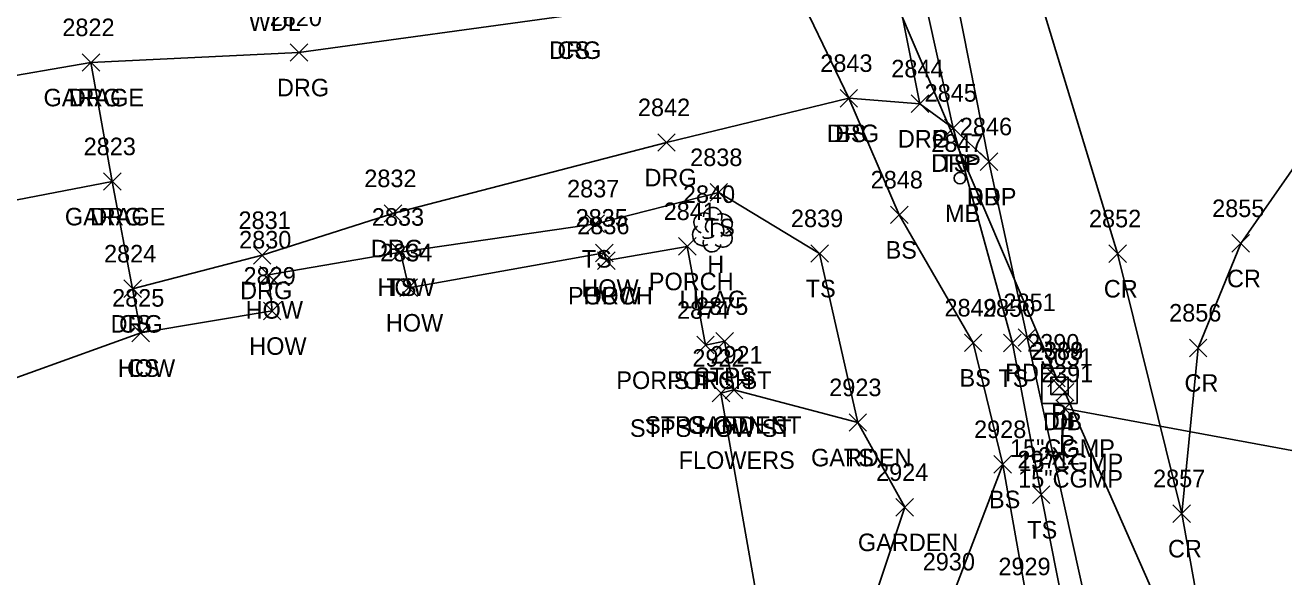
# Model space of a CAD drawing. Extents: x 1504228 to 1506103, y 437717 to 440106.
# Drawn here: x 1505128.7 to 1505272.1, y 438016.6 to 438079.5 of the extents above; entities that cross this region are included whole.
import ezdxf

# ---------------------------------------------------------------- set-up
doc = ezdxf.new("R2010")
doc.units = 0
for name, color, linetype in [('D_A', 7, 'Continuous'), ('D_C', 7, 'Continuous'), ('D_I', 7, 'Continuous'), ('D_TIC', 7, 'Continuous'), ('DCP', 7, 'Continuous'), ('DS', 7, 'Continuous'), ('L_A', 7, 'Continuous'), ('L_C', 7, 'Continuous'), ('L_I', 7, 'Continuous'), ('L_TIC', 7, 'Continuous'), ('LAPB', 7, 'Continuous'), ('LBC', 7, 'Continuous'), ('LBF', 7, 'Continuous'), ('LELB', 7, 'Continuous'), ('LMB', 7, 'Continuous'), ('LTD', 7, 'Continuous'), ('P_A', 7, 'Continuous'), ('P_I', 7, 'Continuous'), ('P_TIC', 7, 'Continuous'), ('PET', 7, 'Continuous'), ('PRC', 7, 'Continuous'), ('R_A', 7, 'Continuous'), ('R_I', 7, 'Continuous'), ('R_TIC', 7, 'Continuous'), ('RDG', 7, 'Continuous'), ('RDP', 7, 'Continuous')]:
    doc.layers.add(name, color=color, linetype=linetype)

msp = doc.modelspace()

# ---------------------------------------------------------------- linework, layer by layer
at = {"layer": 'D_TIC'}
for points in [[(1505245.19, 438038.31), (1505247.19, 438040.31)], [(1505247.19, 438038.31), (1505245.19, 438040.31)], [(1505245.55, 438037.35), (1505247.55, 438039.35)], [(1505247.55, 438037.35), (1505245.55, 438039.35)], [(1505246.15, 438036.69), (1505248.15, 438038.69)], [(1505248.15, 438036.69), (1505246.15, 438038.69)], [(1505246.12, 438034.81), (1505248.12, 438036.81)], [(1505248.12, 438034.81), (1505246.12, 438036.81)]]:
    msp.add_lwpolyline(points, dxfattribs=at)
at = {"layer": 'DCP'}
for points in [[(1505203.94, 438138.28), (1505246.19, 438039.31)], [(1505304.61, 437907.19), (1505247.15, 438037.69)], [(1505247.12, 438035.81), (1505284.73, 438028.89)]]:
    msp.add_lwpolyline(points, dxfattribs=at)
at = {"layer": 'DS'}
for p, q in [((1505244.53, 438040.41), (1505248.53, 438040.41)), ((1505244.53, 438036.41), (1505244.53, 438040.41)), ((1505248.53, 438040.41), (1505248.53, 438036.41)), ((1505245.53, 438037.41), (1505245.53, 438039.41)), ((1505245.53, 438039.41), (1505247.53, 438039.41)), ((1505247.53, 438039.41), (1505247.53, 438037.41)), ((1505247.53, 438037.41), (1505245.53, 438037.41)), ((1505246.54, 438038.41), (1505246.54, 438038.41)), ((1505246.54, 438038.41), (1505246.54, 438038.41)), ((1505248.53, 438036.41), (1505244.53, 438036.41))]:
    msp.add_line(p, q, dxfattribs=at)
at = {"layer": 'L_TIC'}
for points in [[(1505135.2, 438074.26), (1505137.2, 438076.26)], [(1505137.2, 438074.26), (1505135.2, 438076.26)], [(1505221.54, 438070.18), (1505223.54, 438072.18)], [(1505223.54, 438070.18), (1505221.54, 438072.18)], [(1505233.43, 438066.79), (1505235.43, 438068.79)], [(1505235.43, 438066.79), (1505233.43, 438068.79)], [(1505137.63, 438060.69), (1505139.63, 438062.69)], [(1505139.63, 438060.69), (1505137.63, 438062.69)], [(1505206.72, 438059.45), (1505208.72, 438061.45)], [(1505208.72, 438059.45), (1505206.72, 438061.45)], [(1505227.28, 438056.9), (1505229.28, 438058.9)], [(1505229.28, 438056.9), (1505227.28, 438058.9)], [(1505192.7, 438055.88), (1505194.7, 438057.88)], [(1505194.7, 438055.88), (1505192.7, 438057.88)], [(1505170.45, 438052.65), (1505172.45, 438054.65)], [(1505172.45, 438052.65), (1505170.45, 438054.65)], [(1505170.45, 438052.65), (1505172.45, 438054.65)], [(1505172.45, 438052.65), (1505170.45, 438054.65)], [(1505193.67, 438052.55), (1505195.67, 438054.55)], [(1505195.67, 438052.55), (1505193.67, 438054.55)], [(1505203.13, 438053.3), (1505205.13, 438055.3)], [(1505205.13, 438053.3), (1505203.13, 438055.3)], [(1505193.92, 438051.68), (1505195.92, 438053.68)], [(1505195.92, 438051.68), (1505193.92, 438053.68)], [(1505193.92, 438051.68), (1505195.92, 438053.68)], [(1505195.92, 438051.68), (1505193.92, 438053.68)], [(1505218.21, 438052.49), (1505220.21, 438054.49)], [(1505220.21, 438052.49), (1505218.21, 438054.49)], [(1505155.43, 438050.06), (1505157.43, 438052.06)], [(1505157.43, 438050.06), (1505155.43, 438052.06)], [(1505139.95, 438048.47), (1505141.95, 438050.47)], [(1505141.95, 438048.47), (1505139.95, 438050.47)], [(1505171.4, 438048.59), (1505173.4, 438050.59)], [(1505173.4, 438048.59), (1505171.4, 438050.59)], [(1505155.85, 438045.94), (1505157.85, 438047.94)], [(1505157.85, 438045.94), (1505155.85, 438047.94)], [(1505140.87, 438043.43), (1505142.87, 438045.43)], [(1505142.87, 438043.43), (1505140.87, 438045.43)], [(1505140.87, 438043.43), (1505142.87, 438045.43)], [(1505142.87, 438043.43), (1505140.87, 438045.43)], [(1505205.21, 438042.05), (1505207.21, 438044.05)], [(1505207.21, 438042.05), (1505205.21, 438044.05)], [(1505205.21, 438042.05), (1505207.21, 438044.05)], [(1505207.21, 438042.05), (1505205.21, 438044.05)], [(1505207.39, 438042.49), (1505209.39, 438044.49)], [(1505209.39, 438042.49), (1505207.39, 438044.49)], [(1505235.7, 438042.31), (1505237.7, 438044.31)], [(1505237.7, 438042.31), (1505235.7, 438044.31)], [(1505240.16, 438042.28), (1505242.16, 438044.28)], [(1505242.16, 438042.28), (1505240.16, 438044.28)], [(1505208.45, 438036.94), (1505210.45, 438038.94)], [(1505210.45, 438036.94), (1505208.45, 438038.94)], [(1505208.45, 438036.94), (1505210.45, 438038.94)], [(1505210.45, 438036.94), (1505208.45, 438038.94)], [(1505206.97, 438036.59), (1505208.97, 438038.59)], [(1505208.97, 438036.59), (1505206.97, 438038.59)], [(1505206.97, 438036.59), (1505208.97, 438038.59)], [(1505208.97, 438036.59), (1505206.97, 438038.59)], [(1505222.56, 438033.23), (1505224.56, 438035.23)], [(1505224.56, 438033.23), (1505222.56, 438035.23)], [(1505222.56, 438033.23), (1505224.56, 438035.23)], [(1505224.56, 438033.23), (1505222.56, 438035.23)], [(1505239.06, 438028.46), (1505241.06, 438030.46)], [(1505241.06, 438028.46), (1505239.06, 438030.46)], [(1505239.06, 438028.46), (1505241.06, 438030.46)], [(1505241.06, 438028.46), (1505239.06, 438030.46)], [(1505243.45, 438025), (1505245.45, 438027)], [(1505245.45, 438025), (1505243.45, 438027)], [(1505227.9, 438023.57), (1505229.9, 438025.57)], [(1505229.9, 438023.57), (1505227.9, 438025.57)]]:
    msp.add_lwpolyline(points, dxfattribs=at)
at = {"layer": 'LAPB'}
msp.add_lwpolyline([(1505209.45, 438037.94), (1505223.56, 438034.23), (1505228.9, 438024.57), (1505224.55, 438011.46), (1505217.72, 438002.34), (1505212.61, 438011.05)], dxfattribs=at)
at = {"layer": 'LBC'}
for points in [[(1505112.38, 438071.17), (1505136.2, 438075.26), (1505138.63, 438061.69), (1505114.77, 438057.11)], [(1505141.87, 438044.43), (1505156.85, 438046.94), (1505156.43, 438051.06), (1505171.45, 438053.65), (1505172.4, 438049.59), (1505194.67, 438053.55), (1505194.92, 438052.68)], [(1505207.97, 438037.59), (1505212.61, 438011.05), (1505205.89, 438009.47), (1505199.17, 438008.36), (1505185.69, 438006.19)]]:
    msp.add_lwpolyline(points, dxfattribs=at)
at = {"layer": 'LBF'}
for points in [[(1505194.92, 438052.68), (1505204.13, 438054.3), (1505206.21, 438043.05)], [(1505206.21, 438043.05), (1505208.39, 438043.49), (1505209.45, 438037.94), (1505207.97, 438037.59)]]:
    msp.add_lwpolyline(points, dxfattribs=at)
at = {"layer": 'LELB'}
for points in [[(1505216.6, 438137.56), (1505223.94, 438121.39), (1505226.12, 438115.18), (1505227.83, 438097.73), (1505234.43, 438067.79), (1505241.16, 438043.28), (1505244.45, 438026), (1505250.2, 437996.89), (1505253.81, 437956.77), (1505254.12, 437944.47)], [(1505216.57, 438127.72), (1505214.62, 438113.72), (1505216.78, 438101.68), (1505215.58, 438085.68), (1505222.54, 438071.18), (1505228.28, 438057.9), (1505236.7, 438043.31), (1505240.06, 438029.46), (1505242.84, 438013.82), (1505243.25, 437995.87), (1505245.52, 437984.14), (1505242.01, 437964.24)], [(1505140.95, 438049.47), (1505141.87, 438044.43), (1505120.78, 438036.84), (1505092.98, 438031.32), (1505082, 438032.27), (1505079.97, 438044.77), (1505101.17, 438060.97)], [(1505171.45, 438053.65), (1505193.7, 438056.88), (1505207.72, 438060.45), (1505219.21, 438053.49), (1505223.56, 438034.23)], [(1505240.06, 438029.46), (1505234.29, 438014.37), (1505223.97, 438005.58), (1505209.18, 437997.09), (1505198.65, 437998.99), (1505185.38, 437998.07)]]:
    msp.add_lwpolyline(points, dxfattribs=at)
at = {"layer": 'LMB'}
for p, q in [((1505235.84, 438064.67), (1505237.13, 438064.28)), ((1505235.84, 438062.07), (1505235.84, 438064.67)), ((1505235.84, 438063.77), (1505237.13, 438064.28)), ((1505235.19, 438062.07), (1505235.19, 438062.07))]:
    msp.add_line(p, q, dxfattribs=at)
msp.add_circle((1505235.19, 438062.07), 0.656, dxfattribs=at)
at = {"layer": 'LTD'}
msp.add_line((1505206.97, 438056.25), (1505206.97, 438056.25), dxfattribs=at)
msp.add_line((1505206.97, 438056.25), (1505206.97, 438056.25), dxfattribs=at)
msp.add_arc((1505207.02, 438057.69), 1.05, 335.5272, 180.9563, dxfattribs=at)
for centre, major_axis, ratio, start_param, end_param in [((1505206.18, 438056.92), (1.21, -0.51), 0.895232, 1.570796, 4.712389), ((1505206.77, 438056.71), (-0.208, -0.792), 0.645439, 3.141593, 6.283185), ((1505208.02, 438056.84), (-1.14, -0.48), 0.949671, 1.570796, 4.712389), ((1505205.89, 438055.55), (0.58, -1.04), 0.959034, 3.141593, 6.283185), ((1505207.47, 438056.09), (-0.5, 0.667), 0.989748, 3.141593, 6.283185), ((1505207.97, 438055.42), (-1.09, 0.79), 0.841452, 1.570796, 4.712389), ((1505206.97, 438054.75), (0.26, 1.06), 0.942809, 1.570796, 4.712389), ((1505206.52, 438055.5), (-0.625, -0.083), 0.423636, 0, 3.141593)]:
    msp.add_ellipse(centre, major_axis=major_axis, ratio=ratio, start_param=start_param, end_param=end_param, dxfattribs=at)
at = {"layer": 'P_TIC'}
for points in [[(1505237.5, 438062.96), (1505239.5, 438064.96)], [(1505239.5, 438062.96), (1505237.5, 438064.96)], [(1505266.18, 438053.64), (1505268.18, 438055.64)], [(1505268.18, 438053.64), (1505266.18, 438055.64)], [(1505252.15, 438052.47), (1505254.15, 438054.47)], [(1505254.15, 438052.47), (1505252.15, 438054.47)], [(1505241.84, 438042.92), (1505243.84, 438044.92)], [(1505243.84, 438042.92), (1505241.84, 438044.92)], [(1505261.33, 438041.73), (1505263.33, 438043.73)], [(1505263.33, 438041.73), (1505261.33, 438043.73)], [(1505259.45, 438022.85), (1505261.45, 438024.85)], [(1505261.45, 438022.85), (1505259.45, 438024.85)], [(1505259.45, 438022.85), (1505261.45, 438024.85)], [(1505261.45, 438022.85), (1505259.45, 438024.85)]]:
    msp.add_lwpolyline(points, dxfattribs=at)
at = {"layer": 'PET'}
msp.add_lwpolyline([(1505219.54, 438139.33), (1505225.98, 438121.2), (1505231, 438101.8), (1505238.5, 438063.96), (1505242.84, 438043.92), (1505252.22, 438001.48), (1505261.55, 437954.01), (1505268.81, 437912.53)], dxfattribs=at)
at = {"layer": 'PRC'}
for points in [[(1505229.48, 438143.45), (1505234.69, 438118.1), (1505243.62, 438084.86), (1505253.15, 438053.47), (1505260.45, 438023.85), (1505266.19, 437991.87), (1505273.56, 437955.36), (1505281.38, 437913.2)], [(1505309.59, 438099.12), (1505290.72, 438083.22), (1505277.05, 438068.8), (1505267.18, 438054.64), (1505262.33, 438042.73), (1505260.45, 438023.85)]]:
    msp.add_lwpolyline(points, dxfattribs=at)
at = {"layer": 'R_TIC'}
for points in [[(1505135.2, 438074.26), (1505137.2, 438076.26)], [(1505137.2, 438074.26), (1505135.2, 438076.26)], [(1505158.9, 438075.4), (1505160.9, 438077.4)], [(1505160.9, 438075.4), (1505158.9, 438077.4)], [(1505221.54, 438070.18), (1505223.54, 438072.18)], [(1505223.54, 438070.18), (1505221.54, 438072.18)], [(1505229.63, 438069.56), (1505231.63, 438071.56)], [(1505231.63, 438069.56), (1505229.63, 438071.56)], [(1505229.63, 438069.56), (1505231.63, 438071.56)], [(1505231.63, 438069.56), (1505229.63, 438071.56)], [(1505233.43, 438066.79), (1505235.43, 438068.79)], [(1505235.43, 438066.79), (1505233.43, 438068.79)], [(1505200.77, 438065.14), (1505202.77, 438067.14)], [(1505202.77, 438065.14), (1505200.77, 438067.14)], [(1505237.5, 438062.96), (1505239.5, 438064.96)], [(1505239.5, 438062.96), (1505237.5, 438064.96)], [(1505137.63, 438060.69), (1505139.63, 438062.69)], [(1505139.63, 438060.69), (1505137.63, 438062.69)], [(1505169.6, 438057.05), (1505171.6, 438059.05)], [(1505171.6, 438057.05), (1505169.6, 438059.05)], [(1505154.71, 438052.28), (1505156.71, 438054.28)], [(1505156.71, 438052.28), (1505154.71, 438054.28)], [(1505139.95, 438048.47), (1505141.95, 438050.47)], [(1505141.95, 438048.47), (1505139.95, 438050.47)]]:
    msp.add_lwpolyline(points, dxfattribs=at)
at = {"layer": 'RDG'}
for points in [[(1505226.01, 438093.52), (1505215.58, 438085.68), (1505190.9, 438080.66), (1505159.9, 438076.4), (1505136.2, 438075.26)], [(1505138.63, 438061.69), (1505140.95, 438049.47), (1505155.71, 438053.28), (1505170.6, 438058.05), (1505201.77, 438066.14), (1505222.54, 438071.18), (1505230.63, 438070.56)]]:
    msp.add_lwpolyline(points, dxfattribs=at)
at = {"layer": 'RDP'}
msp.add_lwpolyline([(1505231, 438101.8), (1505227.83, 438097.73), (1505226.01, 438093.52), (1505230.63, 438070.56), (1505234.43, 438067.79), (1505238.5, 438063.96)], dxfattribs=at)

# ---------------------------------------------------------------- texts
at = {"layer": 'D_A'}
for s, p in [('P', (1505245.57, 438034.31)), ('DIB', (1505244.65, 438033.35)), ('DI', (1505245.59, 438033.41)), ('P', (1505246.52, 438032.69)), ('P', (1505246.5, 438030.81))]:
    msp.add_text(s, height=2, dxfattribs=at).set_placement(p)
at = {"layer": 'D_C'}
for s, p in [('15"CGMP', (1505240.89, 438030.31)), ('15"CGMP', (1505241.85, 438028.69)), ('2X2', (1505244.11, 438029.41)), ('15"CGMP', (1505241.82, 438026.81))]:
    msp.add_text(s, height=2, dxfattribs=at).set_placement(p)
at = {"layer": 'D_I'}
for s, p in [('2390', (1505242.85, 438042.31)), ('2388', (1505243.28, 438041.41)), ('2389', (1505243.28, 438041.35)), ('3031', (1505244.37, 438040.69)), ('2391', (1505244.43, 438038.81))]:
    msp.add_text(s, height=2, dxfattribs=at).set_placement(p)
at = {"layer": 'L_A'}
for s, p in [('WDL', (1505154.17, 438078.86)), ('CS', (1505189.34, 438075.66)), ('GARAGE', (1505130.8, 438070.26)), ('BS', (1505220.98, 438066.18)), ('TS', (1505232.84, 438062.79)), ('MB', (1505233.49, 438057.07)), ('GARAGE', (1505133.23, 438056.69)), ('TS', (1505206.13, 438055.45)), ('BS', (1505226.72, 438052.9)), ('TS', (1505192.11, 438051.88)), ('H', (1505206.41, 438051.25)), ('HOW', (1505168.84, 438048.65)), ('TS', (1505169.86, 438048.65)), ('HOW', (1505192.06, 438048.55)), ('PORCH', (1505199.75, 438049.3)), ('TS', (1505217.62, 438048.49)), ('PORCH', (1505190.54, 438047.68)), ('HOW', (1505192.3, 438047.68)), ('HOW', (1505153.82, 438046.06)), ('CS', (1505139.4, 438044.47)), ('HOW', (1505169.79, 438044.59)), ('HOW', (1505154.23, 438041.94)), ('HOW', (1505139.26, 438039.43)), ('CS', (1505140.31, 438039.43)), ('STPS', (1505204.91, 438038.49)), ('BS', (1505235.14, 438038.31)), ('TS', (1505239.57, 438038.28)), ('POR STPS ST', (1505196.05, 438038.05)), ('PORCH', (1505201.84, 438038.05)), ('STPS HOW ST', (1505197.6, 438032.59)), ('STPS GDN ST', (1505199.32, 438032.94)), ('GARDEN', (1505204.12, 438032.94)), ('HOW', (1505205.35, 438032.59)), ('GARDEN', (1505218.23, 438029.23)), ('TS', (1505221.97, 438029.23)), ('BS', (1505238.5, 438024.46)), ('BS', (1505238.5, 438024.46)), ('TS', (1505242.86, 438021)), ('GARDEN', (1505223.57, 438019.57))]:
    msp.add_text(s, height=2, dxfattribs=at).set_placement(p)
at = {"layer": 'L_C'}
for s, p in [('LILAC', (1505203.25, 438047.25)), ('FLOWERS', (1505203.15, 438028.94))]:
    msp.add_text(s, height=2, dxfattribs=at).set_placement(p)
at = {"layer": 'L_I'}
for s, p in [('2822', (1505132.94, 438078.26)), ('2843', (1505219.28, 438074.18)), ('2845', (1505231.17, 438070.79)), ('2823', (1505135.37, 438064.69)), ('2847', (1505231.93, 438065.07)), ('2838', (1505204.46, 438063.45)), ('2837', (1505190.44, 438059.88)), ('2848', (1505225.02, 438060.9)), ('2840', (1505203.63, 438059.25)), ('2841', (1505201.44, 438057.3)), ('2833', (1505168.2, 438056.65)), ('2833', (1505168.2, 438056.65)), ('2835', (1505191.41, 438056.55)), ('2836', (1505191.6, 438055.68)), ('2836', (1505191.6, 438055.68)), ('2839', (1505215.94, 438056.49)), ('2830', (1505153.08, 438054.06)), ('2834', (1505169.14, 438052.59)), ('2824', (1505137.69, 438052.47)), ('2829', (1505153.58, 438049.94)), ('2825', (1505138.61, 438047.43)), ('2825', (1505138.61, 438047.43)), ('2874', (1505202.96, 438046.05)), ('2874', (1505202.96, 438046.05)), ('2875', (1505205.13, 438046.49)), ('2849', (1505233.43, 438046.31)), ('2850', (1505237.81, 438046.28)), ('2922', (1505204.71, 438040.59)), ('2922', (1505204.71, 438040.59)), ('2921', (1505206.76, 438040.94)), ('2921', (1505206.76, 438040.94)), ('2923', (1505220.3, 438037.23)), ('2923', (1505220.3, 438037.23)), ('2928', (1505236.8, 438032.46)), ('2928', (1505236.8, 438032.46)), ('2971', (1505241.75, 438029)), ('2924', (1505225.64, 438027.57)), ('2930', (1505230.95, 438017.37)), ('2929', (1505239.57, 438016.82))]:
    msp.add_text(s, height=2, dxfattribs=at).set_placement(p)
at = {"layer": 'P_A'}
for s, p in [('RDP', (1505235.98, 438058.96)), ('CR', (1505251.58, 438048.47)), ('CR', (1505265.61, 438049.64)), ('RDP', (1505240.33, 438038.92)), ('CR', (1505260.77, 438037.73)), ('CR', (1505258.89, 438018.85)), ('CR', (1505258.89, 438018.85))]:
    msp.add_text(s, height=2, dxfattribs=at).set_placement(p)
at = {"layer": 'P_I'}
for s, p in [('2846', (1505235.18, 438066.96)), ('2855', (1505263.92, 438057.64)), ('2852', (1505249.89, 438056.47)), ('2851', (1505240.15, 438046.92)), ('2856', (1505259.02, 438045.73)), ('2857', (1505257.19, 438026.85)), ('2857', (1505257.19, 438026.85))]:
    msp.add_text(s, height=2, dxfattribs=at).set_placement(p)
at = {"layer": 'R_A'}
for s, p in [('DRG', (1505188.39, 438075.66)), ('DRG', (1505157.39, 438071.4)), ('DRG', (1505133.69, 438070.26)), ('DRG', (1505220.03, 438066.18)), ('DRG', (1505228.12, 438065.56)), ('DRP', (1505228.12, 438065.56)), ('DRP', (1505231.92, 438062.79)), ('DRG', (1505199.26, 438061.14)), ('DRP', (1505235.98, 438058.96)), ('DRG', (1505136.12, 438056.69)), ('DRG', (1505168.09, 438053.05)), ('DRG', (1505153.19, 438048.28)), ('DRG', (1505138.44, 438044.47))]:
    msp.add_text(s, height=2, dxfattribs=at).set_placement(p)
at = {"layer": 'R_I'}
for s, p in [('2820', (1505156.56, 438079.4)), ('2822', (1505132.94, 438078.26)), ('2843', (1505219.28, 438074.18)), ('2844', (1505227.37, 438073.56)), ('2844', (1505227.37, 438073.56)), ('2845', (1505231.17, 438070.79)), ('2842', (1505198.51, 438069.14)), ('2846', (1505235.18, 438066.96)), ('2823', (1505135.37, 438064.69)), ('2832', (1505167.34, 438061.05)), ('2831', (1505153.01, 438056.28)), ('2824', (1505137.69, 438052.47))]:
    msp.add_text(s, height=2, dxfattribs=at).set_placement(p)

doc.saveas('drawing.dxf')
